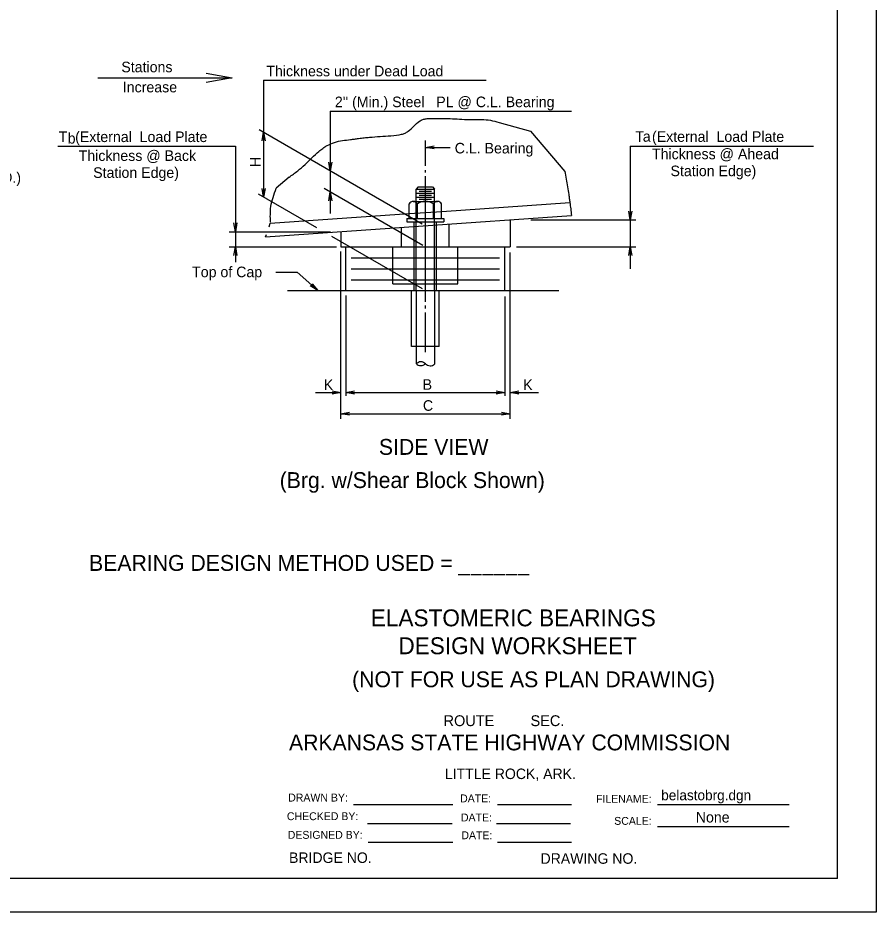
# Model space of a CAD drawing. Extents: x 113 to 232, y -103 to -27.
# Drawn here: x 165.17 to 171.92, y -42.01 to -34.97 of the extents above; entities that cross this region are included whole.
import ezdxf

# ---------------------------------------------------------------- set-up
doc = ezdxf.new("R2010")
doc.units = 0
for name, color, linetype in [('1', 7, 'Continuous'), ('B_Border', 7, 'Continuous'), ('B_Dimension', 7, 'Continuous'), ('B_No_Plot', 7, 'Continuous')]:
    doc.layers.add(name, color=color, linetype=linetype)

msp = doc.modelspace()

# ---------------------------------------------------------------- linework, layer by layer
at = {"layer": '1'}
for p, q in [((165.7965, -35.4465), (166.8545, -35.4465)), ((167.1007, -35.4656), (168.8539, -35.4656)), ((167.1007, -35.4656), (167.1007, -35.8751)), ((167.6254, -35.7078), (167.6254, -36.1782)), ((167.6255, -35.7078), (169.5254, -35.7078)), ((168.9543, -35.7969), (169.201, -35.8652)), ((168.3506, -36.5969), (167.0667, -35.8555)), ((167.1007, -35.8751), (167.1007, -36.3856)), ((169.201, -35.8652), (169.4714, -36.1824)), ((168.3745, -36.1402), (168.3745, -35.9404)), ((165.4817, -35.9839), (166.8796, -35.9839)), ((166.8796, -35.9839), (166.8796, -36.6572)), ((168.3745, -35.9942), (168.5687, -35.9942)), ((169.9875, -35.9839), (169.9875, -36.564)), ((169.9875, -35.9839), (171.4293, -35.9839)), ((167.3021, -36.2289), (167.2009, -36.3161)), ((167.6255, -36.1782), (167.6255, -36.3449)), ((168.3745, -36.1919), (168.3745, -36.1731)), ((168.3745, -37.2097), (168.3745, -36.2201)), ((168.3179, -36.3052), (168.3015, -36.3215)), ((168.3179, -36.3052), (168.431, -36.3052)), ((168.431, -36.3052), (168.4474, -36.3215)), ((167.5191, -36.6272), (167.0599, -36.362)), ((168.3545, -36.7658), (167.5782, -36.3176)), ((167.6255, -36.3449), (167.6255, -36.514)), ((168.3015, -36.4187), (168.3015, -36.3215)), ((168.3015, -36.3215), (168.4474, -36.3215)), ((168.3015, -36.3539), (168.4474, -36.3539)), ((168.3259, -36.3379), (168.423, -36.3379)), ((168.3259, -36.3703), (168.423, -36.3703)), ((168.4474, -36.4187), (168.4474, -36.3215)), ((168.2471, -36.5525), (168.2471, -36.437)), ((168.2792, -36.4187), (168.47, -36.4187)), ((168.3015, -36.3863), (168.4474, -36.3863)), ((168.3015, -37.1211), (168.3015, -36.4187)), ((168.3115, -36.5525), (168.3115, -36.437)), ((168.3259, -36.4026), (168.423, -36.4026)), ((168.4376, -36.5525), (168.4376, -36.437)), ((168.4474, -37.1211), (168.4474, -36.4187)), ((168.5022, -36.5525), (168.5022, -36.437)), ((168.5034, -36.4972), (169.5118, -36.4267)), ((167.154, -36.5914), (168.2473, -36.5151)), ((168.2473, -36.5151), (168.5034, -36.4972)), ((167.1173, -36.6984), (169.5251, -36.5302)), ((167.1441, -36.6204), (167.154, -36.5914)), ((168.2286, -36.5525), (168.5203, -36.5525)), ((168.2286, -36.5525), (168.2286, -36.5785)), ((168.2286, -36.5785), (168.5203, -36.5785)), ((168.286, -36.6168), (168.286, -36.5789)), ((168.463, -36.6044), (168.463, -36.5789)), ((168.5203, -36.5525), (168.5203, -36.5785)), ((169.041, -36.564), (169.041, -36.7773)), ((169.2049, -36.564), (170.0302, -36.564)), ((169.9875, -36.564), (169.9875, -36.7773)), ((166.8311, -36.6572), (167.6269, -36.6572)), ((166.8796, -36.6572), (166.8796, -36.7773)), ((167.7079, -36.6572), (167.7079, -36.7773)), ((168.187, -36.7773), (168.187, -36.6237)), ((168.286, -36.7773), (168.286, -36.6168)), ((168.463, -36.7771), (168.463, -36.6044)), ((168.562, -36.7773), (168.562, -36.5975)), ((167.1173, -36.6984), (167.1241, -36.6785)), ((168.3515, -37.1079), (167.6378, -36.6958)), ((166.8311, -36.7773), (167.6752, -36.7773)), ((166.8796, -36.7773), (166.8796, -36.898)), ((167.7079, -36.7773), (169.041, -36.7773)), ((167.7495, -37.1211), (167.7495, -36.7773)), ((168.1193, -37.0689), (168.1193, -36.7773)), ((168.286, -37.0689), (168.286, -36.7773)), ((168.463, -37.0689), (168.463, -36.7771)), ((168.6296, -37.0689), (168.6296, -36.7771)), ((168.9994, -37.1211), (168.9994, -36.7773)), ((169.0921, -36.7773), (170.0302, -36.7773)), ((169.9875, -36.7773), (169.9875, -36.9502)), ((167.7079, -38.129), (167.7079, -36.814)), ((167.7912, -36.8633), (168.1193, -36.8633)), ((168.1193, -36.8633), (168.6296, -36.8633)), ((168.2844, -36.8633), (168.4618, -36.8633)), ((168.6296, -36.8633), (168.9577, -36.8633)), ((169.041, -38.129), (169.041, -36.8206)), ((167.1986, -36.9759), (167.3654, -36.9759)), ((167.3654, -36.9759), (167.5276, -37.1211)), ((167.7912, -36.9493), (168.1193, -36.9493)), ((168.1193, -36.9493), (168.6296, -36.9493)), ((168.2844, -36.9493), (168.4618, -36.9493)), ((168.6296, -36.9493), (168.9577, -36.9493)), ((167.7912, -37.0352), (168.1193, -37.0352)), ((168.1193, -37.0352), (168.6296, -37.0352)), ((168.1193, -37.0689), (168.6296, -37.0689)), ((168.2844, -37.0352), (168.4618, -37.0352)), ((168.286, -37.1211), (168.286, -37.0689)), ((168.463, -37.1211), (168.463, -37.0689)), ((168.6296, -37.0352), (168.9577, -37.0352)), ((167.29, -37.1211), (169.4244, -37.1211)), ((168.266, -37.5614), (168.266, -37.1211)), ((168.3015, -37.1211), (168.3015, -37.5614)), ((168.4474, -37.1211), (168.4474, -37.5614)), ((168.483, -37.5614), (168.483, -37.1211)), ((167.7495, -37.1591), (167.7495, -37.9479)), ((168.9994, -37.1685), (168.9994, -37.9479)), ((168.3745, -37.2613), (168.3745, -37.2379)), ((168.3745, -37.6054), (168.3745, -37.292)), ((168.483, -37.5614), (168.266, -37.5614)), ((168.3015, -37.5614), (168.3015, -37.6956)), ((168.4473, -37.5614), (168.4473, -37.6989)), ((167.5093, -37.9228), (167.7089, -37.9228)), ((167.7495, -37.9228), (168.9994, -37.9228)), ((169.041, -37.9228), (169.2663, -37.9228)), ((167.7079, -38.0895), (169.041, -38.0895)), ((166.7689, -41.7474), (164.4633, -41.7474))]:
    msp.add_line(p, q, dxfattribs=at)
msp.add_lwpolyline([(166.6493, -35.4104), (166.8545, -35.4465), (166.6493, -35.4827)], dxfattribs=at)
for centre, radius, start, end in [((168.2793, -36.4563), 0.0375, 30.80861, 149.1914), ((168.3746, -36.5368), 0.118, 57.68982, 122.31018), ((168.4699, -36.4564), 0.0376, 30.95728, 149.04272), ((168.338, -37.6608), 0.0504, 223.71346, 316.28654), ((168.3396, -37.7321), 0.0504, 43.71346, 136.28654), ((168.4125, -37.6624), 0.0504, 223.71346, 313.71346)]:
    msp.add_arc(centre, radius, start, end, dxfattribs=at)
for points in [[(167.3021, -36.2289), (167.37, -36.1777), (167.4271, -36.1286), (167.4812, -36.0762), (167.5372, -36.0252), (167.5676, -36.0016), (167.5836, -35.9907), (167.5919, -35.9854), (167.6004, -35.9803), (167.6599, -35.9543), (167.7222, -35.9402), (167.7859, -35.9321), (167.8178, -35.9283), (167.8495, -35.9239), (167.8706, -35.9207), (167.8917, -35.9181), (167.934, -35.9139), (168.0191, -35.9082), (168.104, -35.902), (168.188, -35.8909), (168.2145, -35.882), (168.2388, -35.8668), (168.2838, -35.8265), (168.3291, -35.7878), (168.3537, -35.7747), (168.3807, -35.7687), (168.4182, -35.7669), (168.5311, -35.7667), (168.6064, -35.7695), (168.6816, -35.7734), (168.7158, -35.7746), (168.7501, -35.7748), (168.8187, -35.7752), (168.8869, -35.7805), (168.9543, -35.7969)], [(169.4714, -36.1824), (169.4939, -36.3043), (169.5033, -36.3654), (169.5077, -36.396), (169.5118, -36.4267), (169.5187, -36.4784), (169.5251, -36.5302)], [(167.1552, -36.5832), (167.1585, -36.4598), (167.2009, -36.3161)]]:
    msp.add_spline(points, degree=3, dxfattribs=at)
at = {"layer": 'B_Border'}
for p, q in [((171.618, -41.7481), (171.618, -28.0514)), ((167.808, -41.1648), (168.5913, -41.1648)), ((168.9413, -41.1648), (169.5247, -41.1648)), ((170.2013, -41.1648), (171.238, -41.1648)), ((167.918, -41.3148), (168.5847, -41.3148)), ((168.9347, -41.3148), (169.518, -41.3148)), ((170.2013, -41.3381), (171.238, -41.3381)), ((167.9247, -41.4614), (168.5913, -41.4614)), ((168.9413, -41.4614), (169.5247, -41.4614)), ((171.618, -41.7481), (150.5413, -41.7481))]:
    msp.add_line(p, q, dxfattribs=at)
at = {"layer": 'B_Dimension'}
for points in [[(167.0886, -35.9435), (167.1007, -35.8751), (167.1127, -35.9435)], [(168.4428, -36.0062), (168.3745, -35.9942), (168.4428, -35.9821)], [(167.6375, -36.1099), (167.6254, -36.1782), (167.6134, -36.1099)], [(167.1127, -36.3173), (167.1007, -36.3856), (167.0886, -36.3173)], [(167.6134, -36.4132), (167.6255, -36.3449), (167.6375, -36.4132)], [(169.9995, -36.4957), (169.9875, -36.564), (169.9754, -36.4957)], [(166.8917, -36.5889), (166.8796, -36.6572), (166.8676, -36.5889)], [(166.8676, -36.8456), (166.8796, -36.7773), (166.8917, -36.8456)], [(169.9754, -36.8456), (169.9875, -36.7773), (169.9995, -36.8456)], [(167.4847, -37.0666), (167.5276, -37.1211), (167.4686, -37.0845)], [(167.6405, -37.9108), (167.7089, -37.9228), (167.6405, -37.9349)], [(167.8179, -37.9349), (167.7495, -37.9228), (167.8179, -37.9108)], [(168.931, -37.9108), (168.9994, -37.9228), (168.931, -37.9349)], [(169.1094, -37.9349), (169.041, -37.9228), (169.1094, -37.9108)], [(167.7762, -38.1015), (167.7079, -38.0895), (167.7762, -38.0774)], [(168.9727, -38.0774), (169.041, -38.0895), (168.9727, -38.1015)]]:
    msp.add_lwpolyline(points, dxfattribs=at)
at = {"layer": 'B_No_Plot'}
msp.add_lwpolyline([(149.5897, -27.7878), (171.923, -27.7878), (171.923, -42.0118), (149.5897, -42.0118)], close=True, dxfattribs=at)

# ---------------------------------------------------------------- texts
at = {"layer": '1'}
for s, height, p in [('Stations', 0.08333, (165.9812, -35.4027)), ('Thickness under Dead Load', 0.083334, (167.1225, -35.4348)), ('Increase', 0.08333, (165.9928, -35.561)), ("2'' (Min.) Steel   PL @ C.L. Bearing", 0.083334, (167.6622, -35.6775)), ('T  (External  Load Plate', 0.083334, (165.4877, -35.952)), ('b', 0.0833, (165.5586, -35.9642)), ('T  (External  Load Plate', 0.083334, (170.0286, -35.9504)), ('a', 0.0833, (170.0865, -35.9493)), ('C.L. Bearing', 0.083334, (168.6055, -36.0415)), ('Thickness @ Back', 0.083334, (165.6452, -36.1005)), ('Thickness @ Ahead', 0.083334, (170.1584, -36.0871)), ('Station Edge)', 0.083334, (165.7595, -36.2338)), (' Station Edge)', 0.083334, (170.2735, -36.2204)), ('SIZE (O.D.)', 0.083334, (164.6097, -36.2727)), ('Top of Cap', 0.08333, (166.5385, -37.0156)), ('K', 0.0833, (167.5745, -37.9036)), ('B', 0.0833, (168.3531, -37.9017)), ('K', 0.0833, (169.1445, -37.9037)), ('C', 0.0833, (168.3555, -38.0668)), ('SIDE VIEW', 0.12483, (168.0086, -38.4133)), ('(Brg. w/Shear Block Shown)', 0.124834, (167.2278, -38.6745)), ('BEARING DESIGN METHOD USED = ______', 0.124834, (165.7274, -39.3265)), ('ELASTOMERIC BEARINGS', 0.133, (167.945, -39.7627)), ('DESIGN WORKSHEET', 0.133, (168.1623, -39.9822)), ('(NOT FOR USE AS PLAN DRAWING)', 0.124834, (167.7979, -40.2422)), ('None', 0.08333, (170.5032, -41.3066))]:
    msp.add_text(s, height=height, dxfattribs=at).set_placement(p)
msp.add_text('H', height=0.0833, rotation=90, dxfattribs=at).set_placement((167.0786, -36.1483))
at = {"layer": 'B_Border'}
for s, height, p in [('ROUTE         SEC. ', 0.08532, (168.518, -40.5481)), ('ARKANSAS STATE HIGHWAY COMMISSION', 0.12466, (167.3013, -40.7389)), ('LITTLE ROCK, ARK.', 0.08266, (168.528, -40.9648)), ('DRAWN BY:', 0.062, (167.2947, -41.1414)), ('DATE:', 0.062, (168.648, -41.1481)), ('FILENAME:', 0.062, (169.718, -41.1514)), ('belastobrg.dgn', 0.08, (170.2313, -41.1314)), ('CHECKED BY:', 0.062, (167.2847, -41.2881)), ('DATE:', 0.062, (168.6547, -41.2981)), ('SCALE:', 0.062, (169.8613, -41.3248)), ('DESIGNED BY:', 0.062, (167.2913, -41.4348)), ('DATE:', 0.062, (168.658, -41.4381)), ('BRIDGE NO.', 0.08266, (167.3013, -41.6248)), ('DRAWING NO.', 0.08266, (169.2813, -41.6314))]:
    msp.add_text(s, height=height, dxfattribs=at).set_placement(p)

doc.saveas('drawing.dxf')
